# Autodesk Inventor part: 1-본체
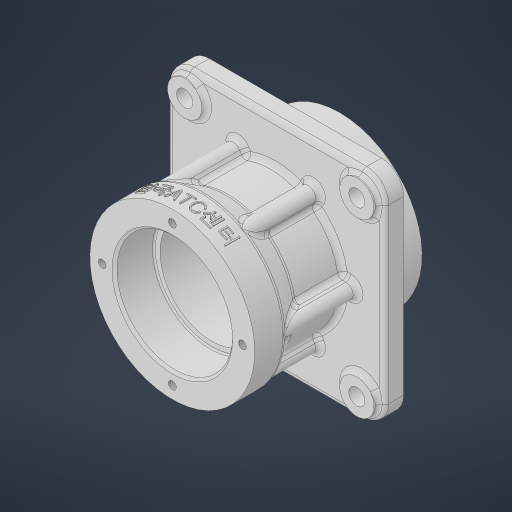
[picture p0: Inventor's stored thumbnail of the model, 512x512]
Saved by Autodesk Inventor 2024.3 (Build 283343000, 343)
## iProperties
Created: 2025-08
Part Number: 1-본체
Material: 일반
Document SubType Name: Modeling
Designer: user
Density: 1 g/cm^3
Appearance: 기본값
Author: user
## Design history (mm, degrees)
sketch "스케치1"
  geometry: L1 (0, 0)-(68, 0); L2 (0, 33.5)-(12, 33.5); L3 (12, 33.5)-(22, 27.5); L4 (0, 33.5)-(0, 0); L5 (22, 27.5)-(55, 27.5); L6 (55, 33.5)-(68, 33.5); L7 (68, 33.5)-(68, 0); L8 (55, 33.5)-(55, 27.5)
  constraints: 16 end point, 3 horizontal, 2 vertical, 1 parallel, 1 perpendicular
  dimensions: "d0" = 68 distance of L1.start L1.end; "d1" = 67 diameter of L2 L1; "d2" = 12 distance of L2.start L2.end; "d4" = 55 diameter of L5 L1; "d5" = 67 diameter of L6 L1; "d6" = 22 horizontal distance of L3.end L2.start; "d7" = 13 distance of L6.start L6.end
revolve "회전1" sketch "스케치1" stored, may be unused: angle "d8" = 90 deg
sketch "스케치2"
  geometry: C1 r 27.5 at (0, 0) reference; C2 r 33.5 at (0, 0) reference; C3 r 38.5 at (0, 0)
  constraints: 1 centre point, 1 coincident
  dimensions: "d9" = 77 diameter of C3
extrude "돌출1" join sketch "스케치2" distance "d10" = 5; taper "d11" = 0 deg
sketch "스케치3"
  geometry: L1 (-44, 44)-(44, 44); L2 (44, 44)-(44, -44); L3 (44, -44)-(-44, -44); L4 (-44, -44)-(-44, 44); C1 r 38.5 at (0, 0) reference; C2 r 27.5 at (0, 0) reference; 2 further points
  constraints: 8 end point, 2 midpoint, 2 parallel, 1 horizontal, 1 horizontal alignment, 1 perpendicular, 1 vertical alignment
  dimensions: "d12" = 88 distance of L2.end L3.end; "d13" = 88 distance of L1.end L2.end
extrude "돌출2" join sketch "스케치3" distance "d14" = 8; taper "d15" = 0 deg
fillet "모깎기1" dims "d16" = 9
sketch "스케치4"
  geometry: C1 r 7 at (-35, 35); C2 r 7 at (35, 35); C3 r 7 at (35, -35); C4 r 7 at (-35, -35); A1 r 9 centre (-35, -35) between (-44, -35) and (-35, -44) reference; A2 r 9 centre (35, -35) between (35, -44) and (44, -35) reference; A3 r 9 centre (35, 35) between (44, 35) and (35, 44) reference; A4 r 9 centre (-35, 35) between (-35, 44) and (-44, 35) reference
  constraints: 4 centre point, 4 coincident
  dimensions: "d17" = 14 diameter of C1; "d18" = 14 diameter of C2; "d19" = 14 diameter of C3; "d20" = 14 diameter of C4
extrude "돌출3" join sketch "스케치4" distance "d21" = 2; taper "d22" = 0 deg
fillet "모깎기2" dims "d23" = 2
sketch "스케치5"
  geometry: A1 r 7 centre (35, 35) between (40.444, 30.6) and (30.6, 40.444) reference; A2 r 7 centre (-35, 35) between (-40.444, 30.6) and (-30.6, 40.444) reference; A3 r 7 centre (35, -35) between (30.6, -40.444) and (40.444, -30.6) reference; A4 r 7 centre (-35, -35) between (-30.6, -40.444) and (-40.444, -30.6) reference; 5 further points
  constraints: 4 coincident
hole "구멍1" sketch "스케치5" at (35, 35), (-35, 35), (35, -35), (-35, -35) diameter "d24" = 6.6; stored, may be unused: countersink angle "d28" = 90 deg, drill point angle "d30" = 118 deg; dims "d25" = 6, "d26" = 4, "d27" = 2, "d29" = 8
fillet "모깎기6" dims "d78" = 2
sketch "스케치6"
  geometry: L1 (0, 0)-(33.5, 0); L2 (30.5, 3)-(27.336, 3); L3 (30.5, -3)-(27.336, -3); A1 r 27.5 centre (0, 0) between (27.336, 3) and (27.336, -3) reference; A2 r 3 centre (30.5, 0) between (27.5, 0) and (30.5, -3); A3 r 3 centre (30.5, 0) between (30.5, 3) and (27.5, 0); A4 r 3 centre (30.5, 0) between (30.5, -3) and (30.5, 3)
  constraints: 11 point on circle, 6 end point, 4 tangent, 3 centre point, 2 horizontal, 1 horizontal alignment, 1 parallel, 1 point on line, 1 other
  dimensions: "d31" = 6 diameter of A2
extrude "돌출4" join sketch "스케치6" stored distance "d32" = 2; taper "d33" = 0 deg
sketch "스케치7"
  geometry: C1 r 33.5 at (0, 0) reference; C2 r 23.5 at (0, 0)
  constraints: 1 centre point, 1 coincident
  dimensions: "d37" = 47 diameter of C2
extrude "돌출5" cut sketch "스케치7" distance "d38" = 16; taper "d39" = 0 deg
sketch "스케치8"
  geometry: C1 r 23.5 at (0, 0) reference; C2 r 21 at (0, 0)
  constraints: 1 centre point, 1 coincident
  dimensions: "d40" = 42 diameter of C2
extrude "돌출6" cut sketch "스케치8" extent not by distance; stored distance "d41" = 0; taper "d42" = 0 deg
sketch "스케치9"
  geometry: C1 r 21 at (0, 0) reference; C2 r 33.5 at (0, 0) reference; C3 r 23.5 at (0, 0)
  constraints: 1 centre point, 1 coincident
  dimensions: "d43" = 47 diameter of C3
extrude "돌출7" cut sketch "스케치9" distance "d44" = 16; taper "d45" = 0 deg
chamfer "모따기1" distance "d46" = 1; stored, may be unused: second distance "d47" = 2, angle "d48" = 45 deg
fillet "모깎기3" dims "d49" = 0.6
sketch "스케치10"
  geometry: L1 (0, 0)-(0, 28.5); C1 r 24.5 at (0, 0) reference; 1 further point
  constraints: 2 end point, 1 coincident, 1 vertical
  dimensions: "d51" = 28.5 distance of L1.start L1.end
hole "구멍2" sketch "스케치10" at (0, 28.5) diameter "d52" = 3.242; stored, may be unused: countersink angle "d56" = 90 deg, drill point angle "d58" = 118 deg; dims "d53" = 8, "d54" = 4, "d55" = 2, "d57" = 10
sketch "스케치11"
  geometry: L1 (0, 0)-(0, 28.5); C1 r 24.5 at (0, 0) reference; 1 further point
  constraints: 2 end point, 1 coincident, 1 vertical
  dimensions: "d62" = 28.5 distance of L1.start L1.end
hole "구멍3" sketch "스케치11" at (0, 28.5) diameter "d63" = 3.242; stored, may be unused: countersink angle "d67" = 90 deg, drill point angle "d69" = 118 deg; dims "d64" = 8, "d65" = 4, "d66" = 2, "d68" = 10
chamfer "모따기2" distance "d73" = 1; stored, may be unused: second distance "d74" = 2, angle "d75" = 45 deg
fillet "모깎기5" dims "d77" = 2
fillet "모깎기7" dims "d79" = 2
fillet "모깎기8" dims "d80" = 2
fillet "모깎기9" dims "d81" = 2
node "작업 평면1"
sketch "스케치12" dims "d0" = 68, "d1" = 67, "d2" = 12, "d4" = 55, "d5" = 67, "d6" = 22, "d7" = 13
  geometry: L1 (6, 33.5)-(-5.446, 33.5) reference; L2 (6, 33.5)-(6, -33.5) reference; L3 (-5.446, 33.5)-(-5.446, 16.75) reference; L4 (-5.446, 16.75)-(-5.446, 33.5) reference; L5 (-5.446, -16.75)-(-5.446, 16.75) reference; L6 (-5.446, -33.5)-(-5.446, -16.75) reference; L7 (-5.446, -16.75)-(-5.446, -33.5) reference; L8 (-5.446, 16.75)-(-5.446, -16.75) reference; L9 (6, 33.5)-(6, -33.5) reference; 2 further points
  constraints: 1 horizontal alignment, 1 other
  dimensions: "d82" = 6 horizontal distance of L1.start point (0, 0)
feature "엠보싱1" sketch "스케치12" dims "d0" = 68, "d1" = 67, "d2" = 12, "d4" = 55, "d5" = 67, "d6" = 22, "d7" = 13, "d83" = 0.5, "d84" = 0
feature "ƌ耀Ǝ耀Ɛ耀ƒ耀Ɣ耀Ɩ耀Ƙ耀ƚ耀" dims "d0" = 68, "d1" = 67, "d2" = 12, "d4" = 55, "d5" = 67, "d6" = 22, "d7" = 13, "d8" = 90 deg, "d9" = 77, "d10" = 5, "d11" = 0, "d12" = 88, "d13" = 88, "d14" = 8, "d15" = 0, "d16" = 9, "d17" = 14, "d18" = 14, "d19" = 14, "d20" = 14, "d21" = 2, "d22" = 0, "d23" = 2, "d24" = 6.6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
feature "Ϲ耀ϻ耀Ͻ耀Ͽ耀Ё耀Ѓ耀Ѕ耀Ї耀" dims "d0" = 68, "d1" = 67, "d2" = 12, "d4" = 55, "d5" = 67, "d6" = 22, "d7" = 13, "d8" = 90 deg, "d9" = 77, "d10" = 5, "d11" = 0, "d12" = 88, "d13" = 88, "d14" = 8, "d15" = 0, "d16" = 9, "d17" = 14, "d18" = 14, "d19" = 14, "d20" = 14, "d21" = 2, "d22" = 0, "d23" = 2, "d24" = 6.6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
node "솔리드1"
pattern_circular "원형 패턴1" dims angle "d35" = 360 deg
pattern_circular "원형 패턴2" dims angle "d60" = 360 deg
pattern_circular "원형 패턴3" dims angle "d71" = 360 deg
node "투영된 루프1"
feature "A9D066F2-1C7D-4E18-AEED-F7BC21143FA4" dims "d24" = 6.6, "d25" = 6, "d26" = 4, "d27" = 2, "d28" = 90 deg, "d29" = 8, "d30" = 118 deg
